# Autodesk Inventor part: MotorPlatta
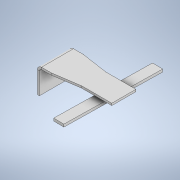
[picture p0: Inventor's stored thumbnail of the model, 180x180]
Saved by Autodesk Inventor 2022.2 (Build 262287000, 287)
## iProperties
Created: 2022-03
Part Number: MotorPlatta
Material: Generic
Document SubType Name: Sheet Metal
Designer: cl
Density: 1 g/cm^3
Sheet Metal Rule: Default
Appearance: Default
Author: cl
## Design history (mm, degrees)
node "Face1"
  sketch "Sketch1"
    geometry: L1 (0, 0)-(0, -186); L2 (0, -186)-(-80, -186); L3 (-80, -186)-(-235, -163); L4 (-235, -163)-(-410, -163); L5 (-410, -163)-(-410, -23); L6 (-410, -23)-(-235, -23); L7 (-235, -23)-(-80, 0); L8 (-80, 0)-(0, 0)
    constraints: 16 end point, 3 perpendicular, 1 horizontal, 1 parallel, 1 vertical
    dimensions: "d0" = 186 distance of L1.start L1.end; "d1" = 80 distance of L1.end L2.end; "d2" = 175 distance of L3.end L4.end; "d3" = 140 distance of L4.end L5.end; "d4" = 23 distance between parallel lines of L2 L4; "d5" = 80 distance from line of L1 L7.end; "d6" = 410 distance between parallel lines of L1 L5; "d7" = 175 distance of L5.end L6.end
node "Flange1"
sketch "Sketch3"
  geometry: L1 (235, -163)-(410, -163) reference; L2 (410, -163)-(410, -23) reference; C1 r 15 at (318, -93); 1 further point
  constraints: 1 centre point
  dimensions: "d19" = 30 diameter of C1; "d20" = 70 distance from line of L1 C1.centre; "d21" = 92 distance from line of L2 C1.centre
extrude "Extrusion1" join sketch "Sketch3" distance "d22" = 28; taper "d23" = 0 deg
sketch "Sketch4"
  geometry: L1 (-32.161, -291.047)-(-42.022, 273.867); L2 (-318, 93)-(-318, -93) reference; L3 (-32.161, -291.047)-(27.83, -290); L4 (27.83, -290)-(17.969, 274.914); L5 (17.969, 274.914)-(-42.022, 273.867); L6 (-83, -70)-(92, -70) reference; L7 (92, -70)-(92, 70) reference
  constraints: 8 end point, 3 perpendicular
  dimensions: "d24" = 1 deg angle of L2 L1; "d25" = 565 distance of L1.start L1.end; "d26" = 60 distance of L1.start L3.end; "d27" = 68 distance from line of L4 L6.end; "d28" = 220 vertical distance of L6.end L3.end
extrude "Extrusion2" join sketch "Sketch4" distance "d29" = 15; taper "d30" = 0 deg
sketch "Sketch5"
  geometry: L1 (17.969, 274.914)-(-42.022, 273.867) reference; L2 (-42.022, 273.867)-(-32.161, -291.047) reference; L3 (-32.161, -291.047)-(27.83, -290) reference; L4 (27.83, -290)-(17.969, 274.914) reference; C1 r 6 at (12.57, -275.264); C2 r 6 at (-26.762, 259.131); 1 further point
  constraints: 2 centre point
  dimensions: "d31" = 12 diameter of C1; "d32" = 15 distance from line of L4 C1.centre; "d33" = 15 distance from line of L3 C1.centre; "d34" = 12 diameter of C2; "d35" = 15 distance from line of L2 C2.centre; "d36" = 15 distance from line of L1 C2.centre
extrude "Extrusion3" join sketch "Sketch5" distance "d37" = 10; taper "d38" = 0 deg
body "Solid1"
face "Plate1" dims "d8" = 12 (= Thickness)
sketch "Sketch2"
  geometry: L1 through (0, 93) direction (0, -1); L2 through (75, 0) direction (1, 0); L3 (150, 0)-(150, 186); L4 (150, 186)-(0, 186)
  constraints: 6 end point, 1 horizontal, 1 perpendicular, 1 vertical
face "Plate2" dims "d8" = 12 (= Thickness), "d9" = 12 (= BendReliefWidth), "d10" = 6 (= BendReliefDepth), "d11" = 24 (= MinimumRemnant), "d12" = 12 (= TransitionRadius), "d13" = 150, "d14" = 90 deg, "d15" = 12 (= BendRadius), "d16" = 48 (= CornerReliefSize), "d17" = 12 (= GapSize), "d18" = 12 (= JacobiRadiusSize), "SeamGap" = 0.01
bend "Bend1" dims "d8" = 12 (= Thickness), "d9" = 12 (= BendReliefWidth), "d10" = 6 (= BendReliefDepth), "d11" = 24 (= MinimumRemnant), "d12" = 12 (= TransitionRadius), "d13" = 150, "d14" = 90 deg, "d15" = 12 (= BendRadius), "SeamGap" = 0.01
feature "Corner1" dims "d13" = 150, "d14" = 90 deg, "d16" = 48 (= CornerReliefSize), "d17" = 12 (= GapSize), "d18" = 12 (= JacobiRadiusSize)
node "Projected Loop1"
other parameters: "Thickness" = 12 (derived), "KFactor" = 4.4, "BendRadius" = 12 (= Thickness), "BendReliefWidth" = 12 (= Thickness), "BendReliefDepth" = 6 (= 0.5 x Thickness), "CornerReliefSize" = 48 (= 4 x Thickness), "MinimumRemnant" = 24 (= 2 x Thickness), "TransitionRadius" = 12 (= BendRadius), "JacobiRadiusSize" = 12 (= BendRadius), "GapSize" = 12 (= Thickness)
